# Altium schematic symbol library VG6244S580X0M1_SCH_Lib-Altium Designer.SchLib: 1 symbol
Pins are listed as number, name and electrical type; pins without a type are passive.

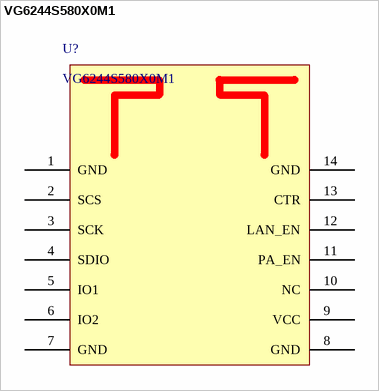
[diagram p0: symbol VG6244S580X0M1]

## VG6244S580X0M1
designator U?
pins: 1 GND, 2 SCS, 3 SCK, 4 SDIO, 5 IO1, 6 IO2, 7 GND, 8 GND, 9 VCC, 10 NC, 11 PA_EN, 12 LAN_EN, 13 CTR, 14 GND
